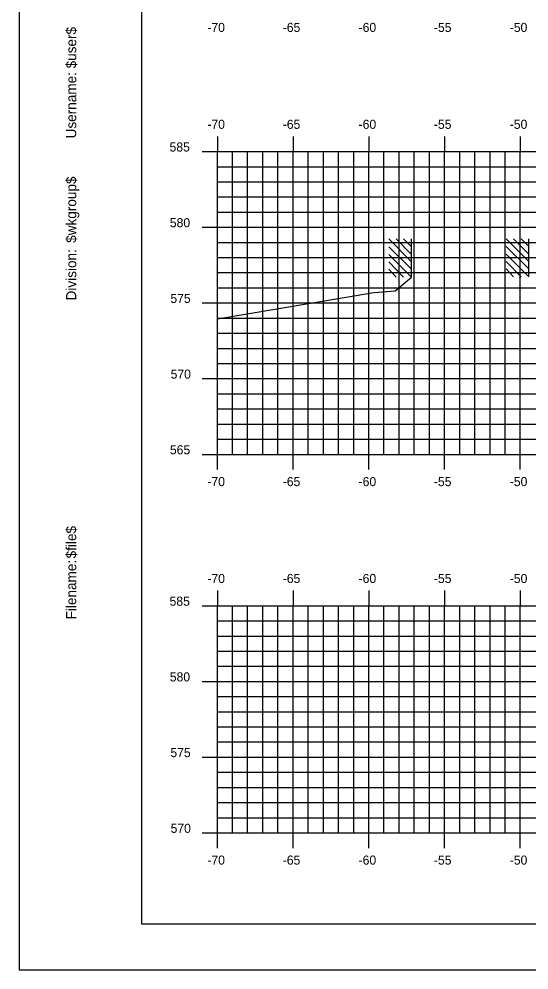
# Model space of a CAD drawing. Extents: x 1048345 to 1048515, y 781148 to 781258.
# Drawn here: x 1048344.7 to 1048378.4, y 781148.2 to 781211 of the extents above; entities that cross this region are included whole.
import ezdxf

# ---------------------------------------------------------------- set-up
doc = ezdxf.new("R2010")
doc.units = 0
for name, color, linetype in [('BORDER', 7, 'Continuous'), ('H_V ANNOTATION', 7, 'Continuous'), ('MAJOR', 7, 'Continuous'), ('MINOR', 7, 'Continuous'), ('PLOT BOUNDARY', 7, 'Continuous'), ('S_Buildings', 7, 'Continuous'), ('S_Roadway_Centerline', 7, 'Continuous')]:
    doc.layers.add(name, color=color, linetype=linetype)

msp = doc.modelspace()

# ---------------------------------------------------------------- linework, layer by layer
at = {"layer": 'BORDER'}
msp.add_lwpolyline([(1048352.833, 781151.252), (1048512.833, 781151.252), (1048512.833, 781256.252), (1048352.833, 781256.252)], close=True, dxfattribs=at)
at = {"layer": 'MAJOR'}
for p, q in [((1048357.832, 781203.254), (1048357.832, 781202.252)), ((1048362.832, 781203.254), (1048362.832, 781202.252)), ((1048367.832, 781203.254), (1048367.832, 781202.252)), ((1048372.832, 781203.254), (1048372.832, 781202.252)), ((1048377.832, 781203.254), (1048377.832, 781202.252)), ((1048356.83, 781202.252), (1048357.832, 781202.252)), ((1048357.832, 781202.252), (1048497.832, 781202.252)), ((1048357.832, 781182.252), (1048357.832, 781202.252)), ((1048357.832, 781202.252), (1048497.832, 781202.252)), ((1048357.832, 781182.252), (1048357.832, 781202.252)), ((1048357.832, 781182.252), (1048357.832, 781202.252)), ((1048357.832, 781202.252), (1048497.832, 781202.252)), ((1048362.832, 781182.252), (1048362.832, 781202.252)), ((1048362.832, 781182.252), (1048362.832, 781202.252)), ((1048367.832, 781182.252), (1048367.832, 781202.252)), ((1048367.832, 781182.252), (1048367.832, 781202.252)), ((1048372.832, 781182.252), (1048372.832, 781202.252)), ((1048372.832, 781182.252), (1048372.832, 781202.252)), ((1048377.832, 781182.252), (1048377.832, 781202.252)), ((1048377.832, 781182.252), (1048377.832, 781202.252)), ((1048356.83, 781197.252), (1048357.832, 781197.252)), ((1048357.832, 781197.252), (1048497.832, 781197.252)), ((1048357.832, 781197.252), (1048497.832, 781197.252)), ((1048356.83, 781192.252), (1048357.832, 781192.252)), ((1048357.832, 781192.252), (1048497.832, 781192.252)), ((1048357.832, 781192.252), (1048497.832, 781192.252)), ((1048356.83, 781187.252), (1048357.832, 781187.252)), ((1048357.832, 781187.252), (1048497.832, 781187.252)), ((1048357.832, 781187.252), (1048497.832, 781187.252)), ((1048356.83, 781182.252), (1048357.832, 781182.252)), ((1048357.832, 781182.252), (1048497.832, 781182.252)), ((1048357.832, 781182.252), (1048497.832, 781182.252)), ((1048357.832, 781182.252), (1048497.832, 781182.252)), ((1048357.832, 781181.25), (1048357.832, 781182.252)), ((1048362.832, 781181.25), (1048362.832, 781182.252)), ((1048367.832, 781181.25), (1048367.832, 781182.252)), ((1048372.832, 781181.25), (1048372.832, 781182.252)), ((1048377.832, 781181.25), (1048377.832, 781182.252)), ((1048357.832, 781173.254), (1048357.832, 781172.252)), ((1048362.832, 781173.254), (1048362.832, 781172.252)), ((1048367.832, 781173.254), (1048367.832, 781172.252)), ((1048372.832, 781173.254), (1048372.832, 781172.252)), ((1048377.832, 781173.254), (1048377.832, 781172.252)), ((1048356.83, 781172.252), (1048357.832, 781172.252)), ((1048357.832, 781172.252), (1048497.832, 781172.252)), ((1048357.832, 781157.252), (1048357.832, 781172.252)), ((1048357.832, 781157.252), (1048357.832, 781172.252)), ((1048357.832, 781172.252), (1048497.832, 781172.252)), ((1048362.832, 781157.252), (1048362.832, 781172.252)), ((1048367.832, 781157.252), (1048367.832, 781172.252)), ((1048372.832, 781157.252), (1048372.832, 781172.252)), ((1048377.832, 781157.252), (1048377.832, 781172.252)), ((1048356.83, 781167.252), (1048357.832, 781167.252)), ((1048357.832, 781167.252), (1048497.832, 781167.252)), ((1048356.83, 781162.252), (1048357.832, 781162.252)), ((1048357.832, 781162.252), (1048497.832, 781162.252)), ((1048356.83, 781157.252), (1048357.832, 781157.252)), ((1048357.832, 781157.252), (1048497.832, 781157.252)), ((1048357.832, 781157.252), (1048497.832, 781157.252)), ((1048357.832, 781156.25), (1048357.832, 781157.252)), ((1048362.832, 781156.25), (1048362.832, 781157.252)), ((1048367.832, 781156.25), (1048367.832, 781157.252)), ((1048372.832, 781156.25), (1048372.832, 781157.252)), ((1048377.832, 781156.25), (1048377.832, 781157.252))]:
    msp.add_line(p, q, dxfattribs=at)
at = {"layer": 'MINOR'}
for p, q in [((1048358.832, 781182.252), (1048358.832, 781202.252)), ((1048358.832, 781182.252), (1048358.832, 781202.252)), ((1048359.832, 781182.252), (1048359.832, 781202.252)), ((1048359.832, 781182.252), (1048359.832, 781202.252)), ((1048360.832, 781182.252), (1048360.832, 781202.252)), ((1048360.832, 781182.252), (1048360.832, 781202.252)), ((1048361.832, 781182.252), (1048361.832, 781202.252)), ((1048361.832, 781182.252), (1048361.832, 781202.252)), ((1048363.832, 781182.252), (1048363.832, 781202.252)), ((1048363.832, 781182.252), (1048363.832, 781202.252)), ((1048364.832, 781182.252), (1048364.832, 781202.252)), ((1048364.832, 781182.252), (1048364.832, 781202.252)), ((1048365.832, 781182.252), (1048365.832, 781202.252)), ((1048365.832, 781182.252), (1048365.832, 781202.252)), ((1048366.832, 781182.252), (1048366.832, 781202.252)), ((1048366.832, 781182.252), (1048366.832, 781202.252)), ((1048368.832, 781182.252), (1048368.832, 781202.252)), ((1048368.832, 781182.252), (1048368.832, 781202.252)), ((1048369.832, 781182.252), (1048369.832, 781202.252)), ((1048369.832, 781182.252), (1048369.832, 781202.252)), ((1048370.832, 781182.252), (1048370.832, 781202.252)), ((1048370.832, 781182.252), (1048370.832, 781202.252)), ((1048371.832, 781182.252), (1048371.832, 781202.252)), ((1048371.832, 781182.252), (1048371.832, 781202.252)), ((1048373.832, 781182.252), (1048373.832, 781202.252)), ((1048373.832, 781182.252), (1048373.832, 781202.252)), ((1048374.832, 781182.252), (1048374.832, 781202.252)), ((1048374.832, 781182.252), (1048374.832, 781202.252)), ((1048375.832, 781182.252), (1048375.832, 781202.252)), ((1048375.832, 781182.252), (1048375.832, 781202.252)), ((1048376.832, 781182.252), (1048376.832, 781202.252)), ((1048376.832, 781182.252), (1048376.832, 781202.252)), ((1048357.832, 781201.252), (1048497.832, 781201.252)), ((1048357.832, 781201.252), (1048497.832, 781201.252)), ((1048357.832, 781201.252), (1048358.834, 781201.252)), ((1048357.832, 781200.252), (1048497.832, 781200.252)), ((1048357.832, 781200.252), (1048497.832, 781200.252)), ((1048357.832, 781200.252), (1048358.834, 781200.252)), ((1048357.832, 781199.252), (1048497.832, 781199.252)), ((1048357.832, 781199.252), (1048497.832, 781199.252)), ((1048357.832, 781199.252), (1048358.834, 781199.252)), ((1048357.832, 781198.252), (1048497.832, 781198.252)), ((1048357.832, 781198.252), (1048497.832, 781198.252)), ((1048357.832, 781198.252), (1048358.834, 781198.252)), ((1048357.832, 781196.252), (1048497.832, 781196.252)), ((1048357.832, 781196.252), (1048497.832, 781196.252)), ((1048357.832, 781196.252), (1048358.834, 781196.252)), ((1048357.832, 781195.252), (1048497.832, 781195.252)), ((1048357.832, 781195.252), (1048497.832, 781195.252)), ((1048357.832, 781195.252), (1048358.834, 781195.252)), ((1048357.832, 781194.252), (1048497.832, 781194.252)), ((1048357.832, 781194.252), (1048497.832, 781194.252)), ((1048357.832, 781194.252), (1048358.834, 781194.252)), ((1048357.832, 781193.252), (1048497.832, 781193.252)), ((1048357.832, 781193.252), (1048497.832, 781193.252)), ((1048357.832, 781193.252), (1048358.834, 781193.252)), ((1048357.832, 781191.252), (1048497.832, 781191.252)), ((1048357.832, 781191.252), (1048497.832, 781191.252)), ((1048357.832, 781191.252), (1048358.834, 781191.252)), ((1048357.832, 781190.252), (1048497.832, 781190.252)), ((1048357.832, 781190.252), (1048497.832, 781190.252)), ((1048357.832, 781190.252), (1048358.834, 781190.252)), ((1048357.832, 781189.252), (1048497.832, 781189.252)), ((1048357.832, 781189.252), (1048497.832, 781189.252)), ((1048357.832, 781189.252), (1048358.834, 781189.252)), ((1048357.832, 781188.252), (1048497.832, 781188.252)), ((1048357.832, 781188.252), (1048497.832, 781188.252)), ((1048357.832, 781188.252), (1048358.834, 781188.252)), ((1048357.832, 781186.252), (1048497.832, 781186.252)), ((1048357.832, 781186.252), (1048497.832, 781186.252)), ((1048357.832, 781186.252), (1048358.834, 781186.252)), ((1048357.832, 781185.252), (1048497.832, 781185.252)), ((1048357.832, 781185.252), (1048497.832, 781185.252)), ((1048357.832, 781185.252), (1048358.834, 781185.252)), ((1048357.832, 781184.252), (1048497.832, 781184.252)), ((1048357.832, 781184.252), (1048497.832, 781184.252)), ((1048357.832, 781184.252), (1048358.834, 781184.252)), ((1048357.832, 781183.252), (1048497.832, 781183.252)), ((1048357.832, 781183.252), (1048497.832, 781183.252)), ((1048357.832, 781183.252), (1048358.834, 781183.252)), ((1048358.832, 781157.252), (1048358.832, 781172.252)), ((1048359.832, 781157.252), (1048359.832, 781172.252)), ((1048360.832, 781157.252), (1048360.832, 781172.252)), ((1048361.832, 781157.252), (1048361.832, 781172.252)), ((1048363.832, 781157.252), (1048363.832, 781172.252)), ((1048364.832, 781157.252), (1048364.832, 781172.252)), ((1048365.832, 781157.252), (1048365.832, 781172.252)), ((1048366.832, 781157.252), (1048366.832, 781172.252)), ((1048368.832, 781157.252), (1048368.832, 781172.252)), ((1048369.832, 781157.252), (1048369.832, 781172.252)), ((1048370.832, 781157.252), (1048370.832, 781172.252)), ((1048371.832, 781157.252), (1048371.832, 781172.252)), ((1048373.832, 781157.252), (1048373.832, 781172.252)), ((1048374.832, 781157.252), (1048374.832, 781172.252)), ((1048375.832, 781157.252), (1048375.832, 781172.252)), ((1048376.832, 781157.252), (1048376.832, 781172.252)), ((1048357.832, 781171.252), (1048497.832, 781171.252)), ((1048357.832, 781171.252), (1048358.834, 781171.252)), ((1048357.832, 781170.252), (1048497.832, 781170.252)), ((1048357.832, 781170.252), (1048358.834, 781170.252)), ((1048357.832, 781169.252), (1048497.832, 781169.252)), ((1048357.832, 781169.252), (1048358.834, 781169.252)), ((1048357.832, 781168.252), (1048497.832, 781168.252)), ((1048357.832, 781168.252), (1048358.834, 781168.252)), ((1048357.832, 781166.252), (1048497.832, 781166.252)), ((1048357.832, 781166.252), (1048358.834, 781166.252)), ((1048357.832, 781165.252), (1048497.832, 781165.252)), ((1048357.832, 781165.252), (1048358.834, 781165.252)), ((1048357.832, 781164.252), (1048497.832, 781164.252)), ((1048357.832, 781164.252), (1048358.834, 781164.252)), ((1048357.832, 781163.252), (1048497.832, 781163.252)), ((1048357.832, 781163.252), (1048358.834, 781163.252)), ((1048357.832, 781161.252), (1048497.832, 781161.252)), ((1048357.832, 781161.252), (1048358.834, 781161.252)), ((1048357.832, 781160.252), (1048497.832, 781160.252)), ((1048357.832, 781160.252), (1048358.834, 781160.252)), ((1048357.832, 781159.252), (1048497.832, 781159.252)), ((1048357.832, 781159.252), (1048358.834, 781159.252)), ((1048357.832, 781158.252), (1048497.832, 781158.252)), ((1048357.832, 781158.252), (1048358.834, 781158.252))]:
    msp.add_line(p, q, dxfattribs=at)
at = {"layer": 'PLOT BOUNDARY'}
msp.add_lwpolyline([(1048344.739, 781148.193), (1048514.739, 781148.193), (1048514.739, 781258.193), (1048344.739, 781258.193)], close=True, dxfattribs=at)
at = {"layer": 'S_Buildings'}
for p, q in [((1048370.656, 781194.967), (1048369.146, 781196.476)), ((1048370.656, 781195.459), (1048369.639, 781196.476)), ((1048370.656, 781195.951), (1048370.131, 781196.476)), ((1048370.656, 781193.95), (1048370.656, 781196.476)), ((1048378.404, 781194.988), (1048376.895, 781196.497)), ((1048378.404, 781195.48), (1048377.387, 781196.497)), ((1048378.404, 781195.972), (1048377.879, 781196.497)), ((1048378.404, 781193.971), (1048378.404, 781196.497)), ((1048370.656, 781194.474), (1048369.146, 781195.951)), ((1048370.656, 781193.95), (1048369.146, 781195.459)), ((1048378.404, 781194.496), (1048376.895, 781195.972)), ((1048378.404, 781193.971), (1048376.895, 781195.48)), ((1048370.131, 781193.95), (1048369.146, 781194.967)), ((1048377.879, 781193.971), (1048376.895, 781194.988)), ((1048369.639, 781193.95), (1048369.146, 781194.474)), ((1048377.387, 781193.971), (1048376.895, 781194.496))]:
    msp.add_line(p, q, dxfattribs=at)
at = {"layer": 'S_Roadway_Centerline'}
msp.add_lwpolyline([(1048357.832, 781191.204), (1048368.173, 781192.931), (1048369.57, 781193.055), (1048370.656, 781193.95)], dxfattribs=at)

# ---------------------------------------------------------------- texts
at = {"layer": 'BORDER'}
for s, p in [('$user$', (1048348.517, 781207.744)), ('Username:', (1048348.517, 781203.12)), ('$wkgroup$', (1048348.517, 781196.222)), ('Division:', (1048348.517, 781192.418)), ('$file$', (1048348.517, 781175.378)), ('Filename:', (1048348.517, 781171.351))]:
    msp.add_text(s, height=0.6696, rotation=90, dxfattribs=at).set_placement(p)
at = {"layer": 'H_V ANNOTATION'}
for s, p in [('-70', (1048357.174, 781210.152)), ('-65', (1048362.15, 781210.152)), ('-60', (1048367.158, 781210.152)), ('-55', (1048372.129, 781210.152)), ('-50', (1048377.137, 781210.152)), ('-70', (1048357.174, 781203.752)), ('-65', (1048362.15, 781203.752)), ('-60', (1048367.158, 781203.752)), ('-55', (1048372.129, 781203.752)), ('-50', (1048377.137, 781203.752)), ('585', (1048354.678, 781202.252)), ('580', (1048354.694, 781197.252)), ('575', (1048354.732, 781192.252)), ('570', (1048354.748, 781187.252)), ('565', (1048354.7, 781182.252)), ('-70', (1048357.174, 781180.152)), ('-65', (1048362.15, 781180.152)), ('-60', (1048367.158, 781180.152)), ('-55', (1048372.129, 781180.152)), ('-50', (1048377.137, 781180.152)), ('-70', (1048357.174, 781173.752)), ('-65', (1048362.15, 781173.752)), ('-60', (1048367.158, 781173.752)), ('-55', (1048372.129, 781173.752)), ('-50', (1048377.137, 781173.752)), ('585', (1048354.678, 781172.252)), ('580', (1048354.694, 781167.252)), ('575', (1048354.732, 781162.252)), ('570', (1048354.748, 781157.252)), ('-70', (1048357.174, 781155.152)), ('-65', (1048362.15, 781155.152)), ('-60', (1048367.158, 781155.152)), ('-55', (1048372.129, 781155.152)), ('-50', (1048377.137, 781155.152))]:
    msp.add_text(s, height=0.6, dxfattribs=at).set_placement(p)
at = {"layer": 'MAJOR'}
for p in [(1048357.828, 781182.252), (1048357.828, 781157.252)]:
    msp.add_text('-', height=0.006, dxfattribs=at).set_placement(p)

doc.saveas('drawing.dxf')
